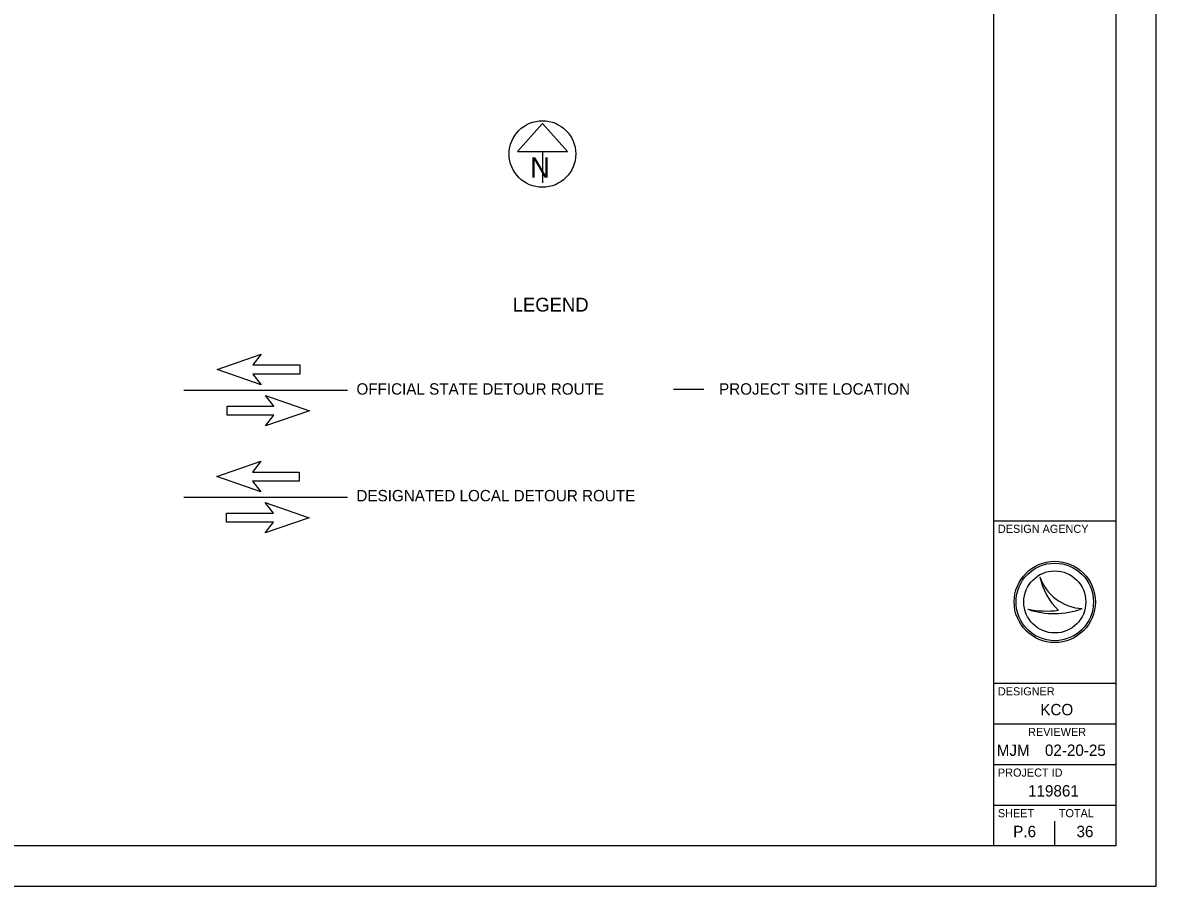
# Model space of a CAD drawing. Extents: x -483 to 680, y 0 to 440.
# Drawn here: x 400.9 to 680, y 0 to 212.6 of the extents above; entities that cross this region are included whole.
import ezdxf

# ---------------------------------------------------------------- set-up
doc = ezdxf.new("R2010")
doc.units = 0
for name, color, linetype in [('Default', 7, 'Continuous'), ('PM_P_Cells', 7, 'Continuous'), ('SH_Border', 7, 'Continuous'), ('SH_Cut_Line', 7, 'Continuous'), ('SH_Data', 7, 'Continuous'), ('SH_Masking', 7, 'Continuous'), ('SH_Text', 7, 'Continuous'), ('UT_P_Electric', 7, 'Continuous'), ('UT_P_Telecom', 7, 'Continuous')]:
    doc.layers.add(name, color=color, linetype=linetype)

msp = doc.modelspace()

# ---------------------------------------------------------------- linework, layer by layer
at = {"layer": 'Default'}
msp.add_line((561.13, 122.42), (568.64, 122.42), dxfattribs=at)
at = {"layer": 'PM_P_Cells'}
for p, q in [((448.8, 127.2), (459.64, 130.96)), ((459.64, 130.96), (457.61, 128.33)), ((459.64, 123.43), (448.8, 127.2)), ((457.61, 128.33), (469.13, 128.33)), ((469.13, 126.07), (457.61, 126.07)), ((457.61, 126.07), (459.64, 123.43)), ((469.13, 128.33), (469.13, 126.07)), ((460.72, 120.85), (471.56, 117.08)), ((462.76, 118.21), (460.72, 120.85)), ((451.24, 115.95), (451.24, 118.21)), ((451.24, 118.21), (462.76, 118.21)), ((462.76, 115.95), (451.24, 115.95)), ((471.56, 117.08), (460.72, 113.32)), ((460.72, 113.32), (462.76, 115.95))]:
    msp.add_line(p, q, dxfattribs=at)
at = {"layer": 'SH_Border'}
for p, q in [((640, 10), (640, 430)), ((640, 90), (670, 90)), ((640, 50), (670, 50)), ((640, 40), (670, 40)), ((640, 30), (670, 30)), ((640, 20), (670, 20))]:
    msp.add_line(p, q, dxfattribs=at)
msp.add_lwpolyline([(30, 430), (670, 430), (670, 10), (30, 10)], close=True, dxfattribs=at)
at = {"layer": 'SH_Cut_Line'}
msp.add_lwpolyline([(0, 0), (680, 0), (680, 440), (0, 440)], close=True, dxfattribs=at)
at = {"layer": 'SH_Data'}
for p, q in [((651.35, 76.19), (651.35, 76.19)), ((651.35, 76.19), (651.35, 76.19)), ((655, 70), (655, 70)), ((648.34, 68.19), (648.34, 68.19)), ((648.34, 68.19), (648.34, 68.19)), ((661.75, 68.37), (661.75, 68.37)), ((661.75, 68.37), (661.75, 68.37)), ((655, 10), (655, 16)), ((647.5, 13.5), (647.5, 13.5))]:
    msp.add_line(p, q, dxfattribs=at)
for radius in [10, 10, 9.54, 9.54, 9.54, 9.54, 7.64, 7.64]:
    msp.add_circle((655, 70), radius, dxfattribs=at)
for centre, radius, start, end in [((662.32, 79.95), 11.6, 198.9257, 198.9319), ((666.93, 79.4), 15.91, 191.6379, 191.6421), ((662.32, 79.95), 11.6, 198.9319, 267.1657), ((666.93, 79.4), 15.91, 191.6421, 226.0947), ((662.32, 79.95), 11.6, 198.9257, 198.9319), ((666.93, 79.4), 15.91, 191.6379, 191.6421), ((662.32, 79.95), 11.6, 198.9319, 267.1657), ((666.93, 79.4), 15.91, 191.6421, 226.0947), ((654.79, 87.4), 20.26, 251.4576, 290.0832), ((654.79, 87.4), 20.26, 251.4576, 290.0832), ((652.96, 93.09), 25.32, 259.4964, 259.4995), ((654.79, 87.4), 20.26, 251.4527, 251.4576), ((652.96, 93.09), 25.32, 259.4995, 276.6672), ((652.96, 93.09), 25.32, 259.4964, 259.4995), ((654.79, 87.4), 20.26, 251.4527, 251.4576), ((652.96, 93.09), 25.32, 259.4995, 276.6672)]:
    msp.add_arc(centre, radius, start, end, dxfattribs=at)
at = {"layer": 'SH_Masking'}
msp.add_circle((528.87, 180.27), 8.2, dxfattribs=at)
at = {"layer": 'SH_Text'}
for p, q in [((528.87, 187.74), (522.72, 180.92)), ((535.02, 180.92), (528.87, 187.74)), ((522.72, 180.92), (535.02, 180.92)), ((528.87, 180.92), (528.87, 173.18)), ((448.68, 100.85), (459.52, 104.62)), ((459.52, 104.62), (457.49, 101.98)), ((459.52, 97.09), (448.68, 100.85)), ((457.49, 101.98), (469.01, 101.98)), ((469.01, 101.98), (469.01, 99.73)), ((469.01, 99.73), (457.49, 99.73)), ((457.49, 99.73), (459.52, 97.09)), ((460.6, 94.5), (471.44, 90.74)), ((462.64, 91.87), (460.6, 94.5)), ((451.12, 89.61), (451.12, 91.87)), ((451.12, 91.87), (462.64, 91.87)), ((462.64, 89.61), (451.12, 89.61)), ((471.44, 90.74), (460.6, 86.98)), ((460.6, 86.98), (462.64, 89.61))]:
    msp.add_line(p, q, dxfattribs=at)
msp.add_circle((528.87, 180.27), 8.2, dxfattribs=at)
at = {"layer": 'UT_P_Electric'}
msp.add_line((440.61, 122.14), (480.9, 122.14), dxfattribs=at)
at = {"layer": 'UT_P_Telecom'}
msp.add_line((440.61, 95.8), (480.9, 95.8), dxfattribs=at)

# ---------------------------------------------------------------- texts
at = {"layer": 'Default'}
for s, height, p in [('LEGEND', 3.4, (521.54, 141.48)), ('OFFICIAL STATE DETOUR ROUTE', 2.8, (483.08, 121.03)), ('PROJECT SITE LOCATION', 2.8, (572.35, 121.03)), ('DESIGNATED LOCAL DETOUR ROUTE', 2.8, (483.08, 94.77))]:
    msp.add_text(s, height=height, dxfattribs=at).set_placement(p)
at = {"layer": 'SH_Data'}
for s, height, p in [('DESIGN AGENCY', 2, (641, 87)), ('DESIGNER', 2, (641, 47)), ('KCO', 2.8, (651.43, 42.1)), ('REVIEWER', 2, (648.44, 37)), ('MJM', 2.8, (640.71, 32.1)), ('02-20-25', 2.8, (652.57, 32.1)), ('PROJECT ID', 2, (641, 27)), ('119861', 2.8, (648.42, 22.1)), ('SHEET', 2, (641, 17)), ('TOTAL', 2, (656, 17)), ('P.6', 2.8, (644.77, 12.1)), ('36', 2.8, (660.35, 12.1))]:
    msp.add_text(s, height=height, dxfattribs=at).set_placement(p)
at = {"layer": 'SH_Text'}
msp.add_text('N', height=5, dxfattribs=at).set_placement((525.85, 174.44))

doc.saveas('drawing.dxf')
